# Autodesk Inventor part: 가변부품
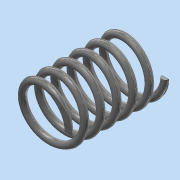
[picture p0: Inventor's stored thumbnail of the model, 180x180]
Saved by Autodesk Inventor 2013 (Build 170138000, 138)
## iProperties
Created: 2018-07
Part Number: 가변부품
Material: 스테인리스강
Document SubType Name: Modeling
Designer: dgall
Density: 8.08 g/cm^3
Mass: 7.54347 g
Surface Area: 18.9168 cm^2
Volume: 0.933598 cm^3
Author: dgall
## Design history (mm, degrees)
sketch "스케치1"
  geometry: L1 (0, 0)-(8, 0); L2 (0, 0)-(0, 28.981); L3 (0, 28.981)-(8, 28.981); C1 r 1 at (8, 0)
  constraints: 6 end point, 2 perpendicular, 1 centre point, 1 coincident, 1 horizontal, 1 vertical alignment
  dimensions: "d0" = 28.98097 distance of L1.start L2.end (derived); "d1" = 16 diameter of L1.end L2; "d2" = 2 diameter of C1
feature "코일1" pitch "d3" = 10; turns "d5" = 6; dims "d4" = 28.98097 (= d0), "d6" = 0, angle "d7" = 90 deg, angle "d8" = 90 deg, "d9" = 0, "d10" = 0
feature "분할1"
node "작업 평면1"
feature "분할2"
node "솔리드1"
other parameters: "d11" = 0
